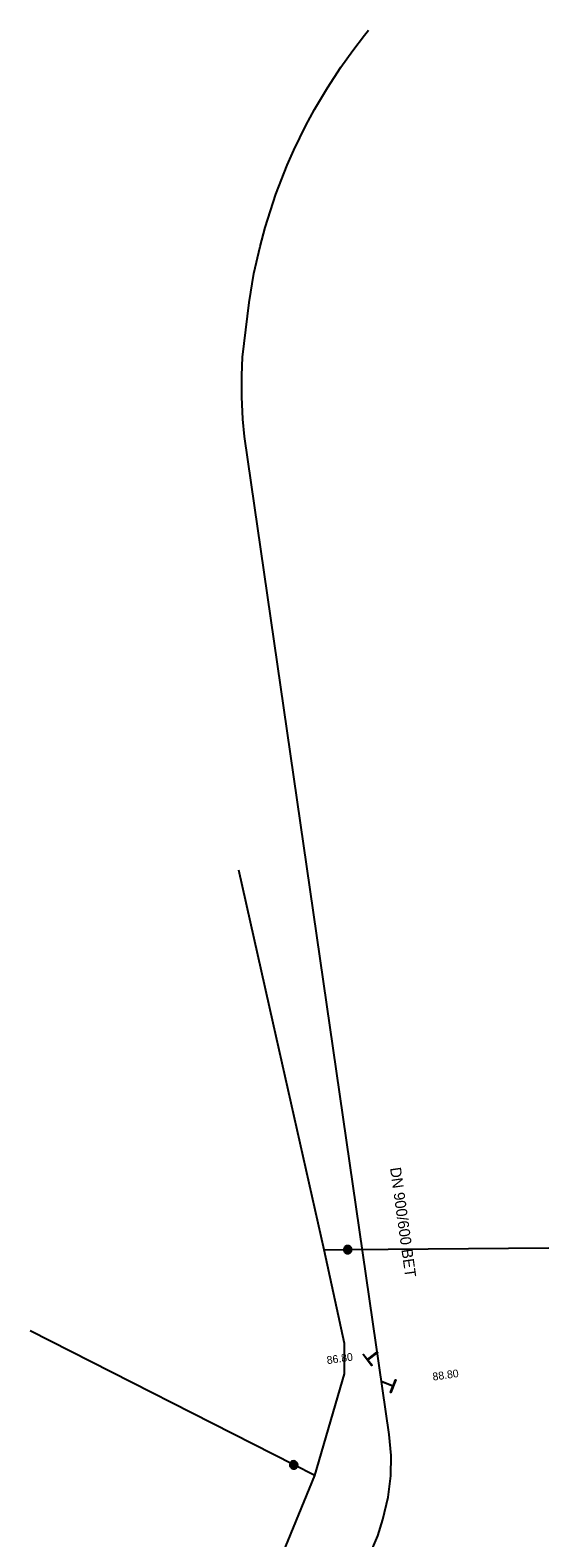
# Model space of a CAD drawing. Extents: x -817726 to -817387, y -1067947 to -1067694.
# Drawn here: x -817483.1 to -817449.9, y -1067790.1 to -1067694 of the extents above; entities that cross this region are included whole.
import ezdxf

# ---------------------------------------------------------------- set-up
doc = ezdxf.new("R2010")
doc.units = 0
doc.layers.add('Default', color=7, linetype='Continuous')
doc.layers.add('Level 0', color=7, linetype='Continuous')

msp = doc.modelspace()

# ---------------------------------------------------------------- linework, layer by layer
at = {"layer": 'Default'}
for points in [[(-817460.892, -1067778.301), (-817460.889, -1067778.321), (-817461.492, -1067778.794), (-817461.231, -1067779.127), (-817461.255, -1067779.145), (-817461.796, -1067778.453), (-817461.772, -1067778.435), (-817461.511, -1067778.77), (-817460.916, -1067778.304), (-817460.892, -1067778.301)], [(-817460.591, -1067780.162), (-817459.892, -1067780.446), (-817459.732, -1067780.052), (-817459.704, -1067780.063), (-817460.034, -1067780.877), (-817460.062, -1067780.866), (-817459.902, -1067780.474), (-817460.613, -1067780.186), (-817460.616, -1067780.166), (-817460.591, -1067780.162)]]:
    msp.add_lwpolyline(points, dxfattribs=at)
for points in [[(-817462.783, -1067771.504), (-817462.72, -1067771.504), (-817462.66, -1067771.536), (-817462.601, -1067771.569), (-817462.567, -1067771.629), (-817462.533, -1067771.689), (-817462.533, -1067771.754), (-817462.533, -1067771.819), (-817462.566, -1067771.879), (-817462.599, -1067771.938), (-817462.658, -1067771.971), (-817462.718, -1067772.004), (-817462.783, -1067772.004), (-817462.848, -1067772.004), (-817462.907, -1067771.971), (-817462.967, -1067771.938), (-817463, -1067771.879), (-817463.033, -1067771.819), (-817463.033, -1067771.754), (-817463.033, -1067771.689), (-817462.999, -1067771.629), (-817462.966, -1067771.569), (-817462.906, -1067771.536), (-817462.846, -1067771.504), (-817462.783, -1067771.504)], [(-817462.783, -1067771.528), (-817462.84, -1067771.528), (-817462.894, -1067771.557), (-817462.949, -1067771.586), (-817462.979, -1067771.641), (-817463.009, -1067771.695), (-817463.009, -1067771.754), (-817463.009, -1067771.813), (-817462.98, -1067771.867), (-817462.95, -1067771.921), (-817462.896, -1067771.951), (-817462.842, -1067771.981), (-817462.783, -1067771.981), (-817462.724, -1067771.981), (-817462.67, -1067771.951), (-817462.616, -1067771.921), (-817462.586, -1067771.867), (-817462.556, -1067771.813), (-817462.556, -1067771.754), (-817462.556, -1067771.695), (-817462.587, -1067771.641), (-817462.618, -1067771.586), (-817462.672, -1067771.557), (-817462.726, -1067771.528), (-817462.783, -1067771.528)], [(-817462.783, -1067771.545), (-817462.73, -1067771.545), (-817462.68, -1067771.572), (-817462.63, -1067771.599), (-817462.602, -1067771.649), (-817462.573, -1067771.699), (-817462.573, -1067771.754), (-817462.573, -1067771.809), (-817462.601, -1067771.859), (-817462.628, -1067771.908), (-817462.678, -1067771.936), (-817462.728, -1067771.964), (-817462.783, -1067771.964), (-817462.837, -1067771.964), (-817462.887, -1067771.936), (-817462.937, -1067771.908), (-817462.965, -1067771.859), (-817462.992, -1067771.809), (-817462.992, -1067771.754), (-817462.992, -1067771.699), (-817462.964, -1067771.649), (-817462.936, -1067771.599), (-817462.886, -1067771.572), (-817462.836, -1067771.545), (-817462.783, -1067771.545)], [(-817462.783, -1067771.567), (-817462.862, -1067771.567), (-817462.916, -1067771.622), (-817462.97, -1067771.677), (-817462.97, -1067771.754), (-817462.97, -1067771.832), (-817462.915, -1067771.887), (-817462.861, -1067771.942), (-817462.783, -1067771.942), (-817462.705, -1067771.942), (-817462.65, -1067771.887), (-817462.595, -1067771.832), (-817462.595, -1067771.754), (-817462.595, -1067771.677), (-817462.65, -1067771.622), (-817462.705, -1067771.567), (-817462.783, -1067771.567)], [(-817462.783, -1067771.59), (-817462.715, -1067771.59), (-817462.667, -1067771.638), (-817462.619, -1067771.686), (-817462.619, -1067771.754), (-817462.619, -1067771.822), (-817462.667, -1067771.87), (-817462.715, -1067771.918), (-817462.783, -1067771.918), (-817462.852, -1067771.918), (-817462.9, -1067771.87), (-817462.947, -1067771.822), (-817462.947, -1067771.754), (-817462.947, -1067771.686), (-817462.9, -1067771.638), (-817462.852, -1067771.59), (-817462.783, -1067771.59)], [(-817462.783, -1067771.609), (-817462.843, -1067771.609), (-817462.886, -1067771.652), (-817462.928, -1067771.694), (-817462.928, -1067771.754), (-817462.928, -1067771.813), (-817462.886, -1067771.856), (-817462.843, -1067771.898), (-817462.783, -1067771.898), (-817462.724, -1067771.898), (-817462.681, -1067771.856), (-817462.639, -1067771.813), (-817462.639, -1067771.754), (-817462.639, -1067771.694), (-817462.681, -1067771.652), (-817462.723, -1067771.609), (-817462.783, -1067771.609)], [(-817462.783, -1067771.629), (-817462.731, -1067771.629), (-817462.694, -1067771.666), (-817462.658, -1067771.702), (-817462.658, -1067771.754), (-817462.658, -1067771.806), (-817462.695, -1067771.843), (-817462.731, -1067771.879), (-817462.783, -1067771.879), (-817462.835, -1067771.879), (-817462.871, -1067771.843), (-817462.908, -1067771.806), (-817462.908, -1067771.754), (-817462.908, -1067771.702), (-817462.872, -1067771.666), (-817462.835, -1067771.629), (-817462.783, -1067771.629)], [(-817462.783, -1067771.652), (-817462.825, -1067771.652), (-817462.855, -1067771.682), (-817462.885, -1067771.712), (-817462.885, -1067771.754), (-817462.885, -1067771.796), (-817462.855, -1067771.826), (-817462.825, -1067771.855), (-817462.783, -1067771.855), (-817462.741, -1067771.855), (-817462.711, -1067771.826), (-817462.682, -1067771.796), (-817462.682, -1067771.754), (-817462.682, -1067771.712), (-817462.711, -1067771.682), (-817462.741, -1067771.652), (-817462.783, -1067771.652)], [(-817462.783, -1067771.67), (-817462.748, -1067771.67), (-817462.723, -1067771.694), (-817462.699, -1067771.719), (-817462.699, -1067771.754), (-817462.699, -1067771.789), (-817462.724, -1067771.814), (-817462.748, -1067771.838), (-817462.783, -1067771.838), (-817462.818, -1067771.838), (-817462.843, -1067771.814), (-817462.867, -1067771.789), (-817462.867, -1067771.754), (-817462.867, -1067771.719), (-817462.843, -1067771.694), (-817462.818, -1067771.67), (-817462.783, -1067771.67)], [(-817462.783, -1067771.692), (-817462.809, -1067771.692), (-817462.827, -1067771.71), (-817462.845, -1067771.728), (-817462.845, -1067771.754), (-817462.845, -1067771.78), (-817462.827, -1067771.798), (-817462.809, -1067771.817), (-817462.783, -1067771.817), (-817462.757, -1067771.817), (-817462.739, -1067771.798), (-817462.72, -1067771.78), (-817462.72, -1067771.754), (-817462.72, -1067771.728), (-817462.739, -1067771.71), (-817462.757, -1067771.692), (-817462.783, -1067771.692)], [(-817462.783, -1067771.715), (-817462.767, -1067771.715), (-817462.755, -1067771.726), (-817462.744, -1067771.738), (-817462.744, -1067771.754), (-817462.744, -1067771.77), (-817462.755, -1067771.782), (-817462.767, -1067771.793), (-817462.783, -1067771.793), (-817462.799, -1067771.793), (-817462.811, -1067771.782), (-817462.822, -1067771.77), (-817462.822, -1067771.754), (-817462.822, -1067771.738), (-817462.811, -1067771.726), (-817462.799, -1067771.715), (-817462.783, -1067771.715)], [(-817462.783, -1067771.731), (-817462.793, -1067771.731), (-817462.8, -1067771.737), (-817462.807, -1067771.744), (-817462.807, -1067771.754), (-817462.807, -1067771.764), (-817462.8, -1067771.771), (-817462.793, -1067771.778), (-817462.783, -1067771.778), (-817462.773, -1067771.778), (-817462.766, -1067771.771), (-817462.76, -1067771.764), (-817462.76, -1067771.754), (-817462.76, -1067771.744), (-817462.766, -1067771.737), (-817462.773, -1067771.731), (-817462.783, -1067771.731)], [(-817466.112, -1067785.262), (-817466.056, -1067785.291), (-817466.018, -1067785.347), (-817465.979, -1067785.403), (-817465.976, -1067785.472), (-817465.973, -1067785.541), (-817466.003, -1067785.599), (-817466.032, -1067785.657), (-817466.089, -1067785.695), (-817466.145, -1067785.733), (-817466.213, -1067785.735), (-817466.281, -1067785.737), (-817466.339, -1067785.708), (-817466.397, -1067785.679), (-817466.435, -1067785.622), (-817466.473, -1067785.566), (-817466.476, -1067785.498), (-817466.478, -1067785.43), (-817466.448, -1067785.372), (-817466.419, -1067785.314), (-817466.362, -1067785.275), (-817466.304, -1067785.237), (-817466.236, -1067785.235), (-817466.169, -1067785.234), (-817466.112, -1067785.262)], [(-817466.123, -1067785.283), (-817466.174, -1067785.257), (-817466.235, -1067785.259), (-817466.297, -1067785.26), (-817466.349, -1067785.295), (-817466.401, -1067785.33), (-817466.428, -1067785.383), (-817466.454, -1067785.435), (-817466.452, -1067785.497), (-817466.45, -1067785.558), (-817466.415, -1067785.609), (-817466.381, -1067785.66), (-817466.329, -1067785.687), (-817466.276, -1067785.714), (-817466.214, -1067785.712), (-817466.153, -1067785.71), (-817466.102, -1067785.675), (-817466.051, -1067785.641), (-817466.024, -1067785.588), (-817465.997, -1067785.535), (-817466, -1067785.473), (-817466.002, -1067785.41), (-817466.037, -1067785.36), (-817466.072, -1067785.309), (-817466.123, -1067785.283)], [(-817466.131, -1067785.299), (-817466.084, -1067785.323), (-817466.051, -1067785.369), (-817466.019, -1067785.416), (-817466.017, -1067785.474), (-817466.014, -1067785.532), (-817466.039, -1067785.581), (-817466.064, -1067785.629), (-817466.111, -1067785.661), (-817466.158, -1067785.693), (-817466.215, -1067785.695), (-817466.272, -1067785.697), (-817466.321, -1067785.672), (-817466.369, -1067785.647), (-817466.401, -1067785.6), (-817466.433, -1067785.553), (-817466.435, -1067785.496), (-817466.437, -1067785.439), (-817466.412, -1067785.39), (-817466.387, -1067785.341), (-817466.34, -1067785.309), (-817466.292, -1067785.277), (-817466.235, -1067785.276), (-817466.178, -1067785.275), (-817466.131, -1067785.299)], [(-817466.141, -1067785.318), (-817466.211, -1067785.283), (-817466.284, -1067785.307), (-817466.357, -1067785.331), (-817466.393, -1067785.4), (-817466.428, -1067785.47), (-817466.404, -1067785.543), (-817466.38, -1067785.617), (-817466.311, -1067785.652), (-817466.242, -1067785.688), (-817466.168, -1067785.664), (-817466.094, -1067785.64), (-817466.059, -1067785.571), (-817466.023, -1067785.501), (-817466.047, -1067785.427), (-817466.071, -1067785.354), (-817466.141, -1067785.318)], [(-817466.151, -1067785.338), (-817466.09, -1067785.37), (-817466.069, -1067785.434), (-817466.049, -1067785.498), (-817466.08, -1067785.559), (-817466.111, -1067785.62), (-817466.175, -1067785.641), (-817466.24, -1067785.662), (-817466.3, -1067785.631), (-817466.361, -1067785.6), (-817466.382, -1067785.535), (-817466.403, -1067785.471), (-817466.372, -1067785.41), (-817466.341, -1067785.349), (-817466.277, -1067785.328), (-817466.212, -1067785.307), (-817466.151, -1067785.338)], [(-817466.16, -1067785.356), (-817466.214, -1067785.329), (-817466.271, -1067785.347), (-817466.327, -1067785.366), (-817466.354, -1067785.419), (-817466.382, -1067785.472), (-817466.363, -1067785.529), (-817466.345, -1067785.586), (-817466.291, -1067785.613), (-817466.238, -1067785.64), (-817466.181, -1067785.622), (-817466.124, -1067785.603), (-817466.097, -1067785.55), (-817466.07, -1067785.497), (-817466.088, -1067785.44), (-817466.107, -1067785.383), (-817466.16, -1067785.356)], [(-817466.169, -1067785.374), (-817466.122, -1067785.398), (-817466.107, -1067785.447), (-817466.091, -1067785.496), (-817466.114, -1067785.542), (-817466.138, -1067785.588), (-817466.187, -1067785.604), (-817466.236, -1067785.62), (-817466.283, -1067785.597), (-817466.328, -1067785.573), (-817466.345, -1067785.524), (-817466.361, -1067785.475), (-817466.337, -1067785.429), (-817466.313, -1067785.382), (-817466.265, -1067785.366), (-817466.216, -1067785.35), (-817466.169, -1067785.374)], [(-817466.18, -1067785.394), (-817466.217, -1067785.375), (-817466.257, -1067785.388), (-817466.297, -1067785.401), (-817466.316, -1067785.439), (-817466.335, -1067785.476), (-817466.322, -1067785.516), (-817466.309, -1067785.556), (-817466.272, -1067785.575), (-817466.234, -1067785.594), (-817466.194, -1067785.582), (-817466.154, -1067785.569), (-817466.135, -1067785.531), (-817466.116, -1067785.493), (-817466.129, -1067785.454), (-817466.142, -1067785.414), (-817466.18, -1067785.394)], [(-817466.187, -1067785.41), (-817466.156, -1067785.426), (-817466.145, -1067785.459), (-817466.135, -1067785.492), (-817466.151, -1067785.523), (-817466.167, -1067785.554), (-817466.2, -1067785.565), (-817466.233, -1067785.576), (-817466.264, -1067785.56), (-817466.295, -1067785.544), (-817466.306, -1067785.511), (-817466.317, -1067785.478), (-817466.301, -1067785.447), (-817466.285, -1067785.415), (-817466.252, -1067785.405), (-817466.219, -1067785.394), (-817466.187, -1067785.41)], [(-817466.197, -1067785.429), (-817466.221, -1067785.418), (-817466.245, -1067785.426), (-817466.27, -1067785.434), (-817466.281, -1067785.457), (-817466.293, -1067785.48), (-817466.285, -1067785.505), (-817466.277, -1067785.529), (-817466.254, -1067785.541), (-817466.231, -1067785.553), (-817466.206, -1067785.545), (-817466.182, -1067785.537), (-817466.17, -1067785.514), (-817466.158, -1067785.491), (-817466.166, -1067785.466), (-817466.174, -1067785.441), (-817466.197, -1067785.429)], [(-817466.208, -1067785.45), (-817466.193, -1067785.458), (-817466.188, -1067785.473), (-817466.183, -1067785.488), (-817466.191, -1067785.503), (-817466.198, -1067785.517), (-817466.214, -1067785.522), (-817466.229, -1067785.527), (-817466.244, -1067785.52), (-817466.258, -1067785.513), (-817466.263, -1067785.497), (-817466.268, -1067785.482), (-817466.261, -1067785.467), (-817466.253, -1067785.453), (-817466.238, -1067785.448), (-817466.222, -1067785.443), (-817466.208, -1067785.45)], [(-817466.215, -1067785.464), (-817466.224, -1067785.46), (-817466.233, -1067785.463), (-817466.242, -1067785.466), (-817466.247, -1067785.475), (-817466.251, -1067785.483), (-817466.248, -1067785.492), (-817466.245, -1067785.502), (-817466.236, -1067785.506), (-817466.228, -1067785.511), (-817466.218, -1067785.508), (-817466.209, -1067785.504), (-817466.205, -1067785.496), (-817466.2, -1067785.487), (-817466.203, -1067785.478), (-817466.206, -1067785.469), (-817466.215, -1067785.464)]]:
    msp.add_open_spline(points, degree=3, dxfattribs=at)
at = {"layer": 'Level 0'}
for p, q in [((-817462.466, -1067695.284), (-817461.717, -1067694.312)), ((-817461.717, -1067694.312), (-817461.45, -1067693.982)), ((-817463.219, -1067696.338), (-817462.466, -1067695.284)), ((-817464.083, -1067697.656), (-817463.219, -1067696.338)), ((-817464.907, -1067699.047), (-817464.083, -1067697.656)), ((-817465.457, -1067700.064), (-817464.907, -1067699.047)), ((-817466.229, -1067701.646), (-817465.457, -1067700.064)), ((-817466.646, -1067702.594), (-817466.229, -1067701.646)), ((-817467.365, -1067704.436), (-817466.646, -1067702.594)), ((-817468.055, -1067706.576), (-817467.365, -1067704.436)), ((-817468.378, -1067707.778), (-817468.055, -1067706.576)), ((-817468.764, -1067709.505), (-817468.378, -1067707.778)), ((-817469.078, -1067711.357), (-817468.764, -1067709.505)), ((-817469.491, -1067714.831), (-817469.078, -1067711.357)), ((-817469.542, -1067716.014), (-817469.491, -1067714.831)), ((-817469.54, -1067717.375), (-817469.542, -1067716.014)), ((-817469.47, -1067718.783), (-817469.54, -1067717.375)), ((-817469.365, -1067719.903), (-817469.47, -1067718.783)), ((-817460.129, -1067783.538), (-817469.365, -1067719.903)), ((-817467.537, -1067757.306), (-817469.732, -1067747.551)), ((-817464.283, -1067771.766), (-817467.537, -1067757.306)), ((-817464.283, -1067771.766), (-817462.783, -1067771.754)), ((-817462.98, -1067777.738), (-817464.283, -1067771.766)), ((-817462.783, -1067771.754), (-817449.947, -1067771.65)), ((-817466.226, -1067785.485), (-817483.05, -1067776.928)), ((-817462.989, -1067779.67), (-817462.98, -1067777.738)), ((-817464.889, -1067786.165), (-817462.989, -1067779.67)), ((-817460.016, -1067784.895), (-817460.129, -1067783.538)), ((-817464.889, -1067786.165), (-817466.226, -1067785.485)), ((-817460.035, -1067786.176), (-817460.016, -1067784.895)), ((-817466.924, -1067791.138), (-817464.889, -1067786.165)), ((-817460.192, -1067787.543), (-817460.035, -1067786.176)), ((-817460.533, -1067788.973), (-817460.192, -1067787.543)), ((-817460.853, -1067790.014), (-817460.533, -1067788.973)), ((-817461.415, -1067791.31), (-817460.853, -1067790.014))]:
    msp.add_line(p, q, dxfattribs=at)

# ---------------------------------------------------------------- texts
for s, height, rotation, p in [('DN 900/600 BET', 0.7, 278, (-817460.087, -1067766.553)), ('86.80', 0.5, 8, (-817464.086, -1067779.061)), ('88.80', 0.5, 8, (-817457.335, -1067780.111))]:
    msp.add_text(s, height=height, rotation=rotation, dxfattribs=at).set_placement(p)

doc.saveas('drawing.dxf')
